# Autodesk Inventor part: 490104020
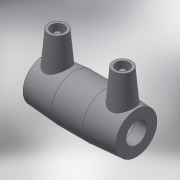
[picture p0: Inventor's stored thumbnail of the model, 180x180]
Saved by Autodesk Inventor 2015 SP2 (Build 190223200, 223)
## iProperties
Created: 2017-06
Part Number: 490104020
Material: Generic
Description: PLASSON COUPLER 20-20
Document SubType Name: Modeling
Designer: KIM
Mass: 55.0731 g
Surface Area: 148.067 cm^2
Volume: 55.0731 cm^3
Density: 1 g/cm^3
Appearance: Default
Author: KIM
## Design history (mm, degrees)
derived "490104.ipt"
feature "Solid1::490104.ipt"
tag "TaggingFeature1"
body "Solid1"
other parameters: "d0" = 76, "d2" = 31, "d3" = 37, "d4" = 25.33333, "d5" = 27.9, "d6" = 19, "d8" = 168 deg, "d10" = 14.8, "d11" = 4.93333, "d13" = 76, "d14" = 17.6296, "d15" = 37, "d16" = 37, "d17" = 19, "d19" = 3.52592, "d20" = 168 deg, "d22" = 29.14, "d23" = 31, "d24" = 28.2658, "d25" = 135 deg, "d26" = 30.4, "d27" = 135 deg, "d29" = 34, "d30" = 14, "d31" = 26.6, "d34" = 5 deg, "d35" = 15, "d39" = 5 deg, "d41" = 4, "d42" = 14, "d43" = 0, "d45" = 4, "d46" = 14, "d47" = 0, "d48" = 3, "d49" = 0, "d50" = 3, "d51" = 0, "d52" = 10.73, "d53" = 2.6825, "L_" = 76, "L_1" = 37, "D_" = 31, "A_" = 34, "d_2" = 12
